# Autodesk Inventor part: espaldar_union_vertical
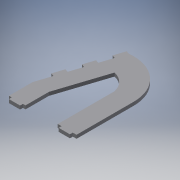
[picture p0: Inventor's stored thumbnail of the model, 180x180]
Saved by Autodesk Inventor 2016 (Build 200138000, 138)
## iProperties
Created: 2017-06
Part Number: espaldar_union_vertical
Material: Generic
Document SubType Name: Modeling
Designer: laboratorioesan
Density: 1 g/cm^3
Appearance: Default
Author: laboratorioesan
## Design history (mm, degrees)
sketch "Sketch1"
  geometry: L1 (0, 0)-(60, 0) reference; L2 (0, 0)-(0, -15.5) reference; L3 (60, -15.5)-(0, -15.5) reference; L4 (60, 0)-(60, -15.5) reference; L5 (266.405, 0)-(326.405, 0) reference; L6 (266.405, 0)-(266.405, -15.5) reference; L7 (326.405, -15.5)-(266.405, -15.5) reference; L8 (326.405, 0)-(326.405, -15.5) reference; L9 (30.902, 267.889)-(12.361, 210.825) reference; L10 (30.902, 267.889)-(13.307, 273.606) reference; L11 (-5.234, 216.542)-(13.307, 273.606) reference; L12 (12.361, 210.825)-(-5.234, 216.542) reference; L13 (71.074, 391.526)-(52.533, 334.463) reference; L14 (71.074, 391.526)-(53.479, 397.243) reference; L15 (34.938, 340.18)-(53.479, 397.243) reference; L16 (52.533, 334.463)-(34.938, 340.18) reference; L17 (111.246, 515.164)-(92.705, 458.1) reference; L18 (111.246, 515.164)-(93.652, 520.88) reference; L19 (75.111, 463.817)-(93.652, 520.88) reference; L20 (92.705, 458.1)-(75.111, 463.817) reference; L21 (0, 172.783)-(111.246, 515.164) reference; L22 (0, 0)-(-15, 0); L23 (-15, 0)-(-15, 126.618); L24 (-15, 126.618)-(111.246, 515.164); L25 (-15, 0)-(73.818, 0); L26 (73.818, 0)-(73.818, 124.907); L27 (73.818, 124.907)-(159.892, 389.815); L28 (326.405, 0)-(346.405, 0); L29 (266.405, 0)-(246.405, 0); L30 (346.405, 0)-(346.405, 302.066); L31 (246.405, 0)-(246.405, 302.066); A1 r 210.681 centre (135.759, 305.913) between (346.405, 302.066) and (111.246, 515.164); A2 r 114.091 centre (134.769, 278.524) between (246.405, 302.066) and (159.892, 389.815)
  constraints: 20 end point, 4 horizontal, 4 point on circle, 3 perpendicular, 2 centre point, 2 point on line, 1 collinear, 1 parallel, 1 vertical
  dimensions: "d1" = 15 distance of L1.start L22.end; "d2" = 20 distance of L5.end L28.end; "d3" = 20 distance of L5.start L29.end; "d4" = 85 distance between parallel lines of L24 L27
extrude "Extrusion1" new body sketch "Sketch1" distance "d5" = 18.5; taper "d6" = 0 deg
body "Solid1"
node "Reference1"
node "Reference2"
node "Reference3"
node "Reference4"
node "Reference5"
node "Reference6"
